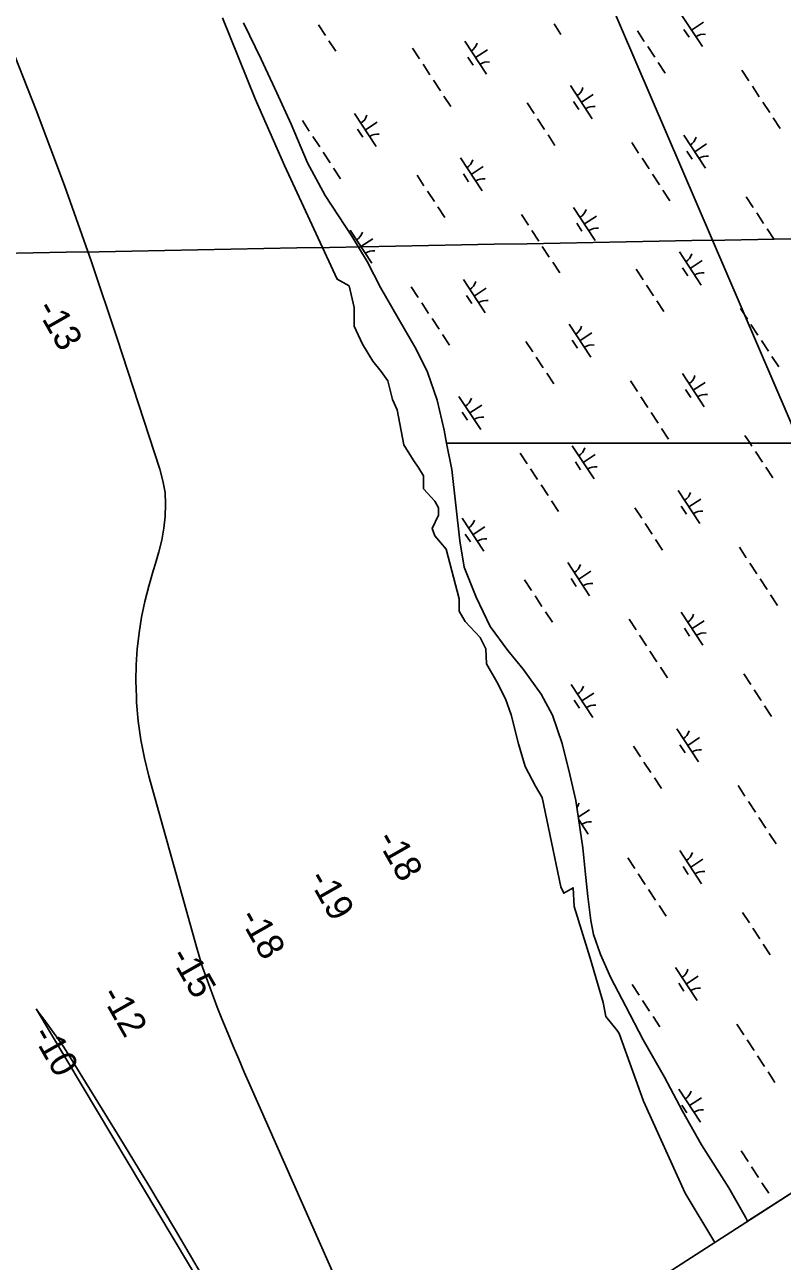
# Model space of a CAD drawing. Extents: x 3945642 to 3966284, y 206476 to 228921.
# Drawn here: x 3959667 to 3960623, y 211105 to 212666 of the extents above; entities that cross this region are included whole.
import ezdxf

# ---------------------------------------------------------------- set-up
doc = ezdxf.new("R2010")
doc.units = 0
for name, color, linetype in [('V-GRID-FRAM', 7, 'Continuous'), ('V-GRID-MAJR', 7, 'Continuous'), ('V-RIVR-EDGE', 7, 'Continuous'), ('V-RIVR-RANG', 7, 'Continuous'), ('V-TOPO-DPTH', 7, 'Continuous'), ('V-TOPO-MINR', 7, 'Continuous'), ('V-UTIL-LINE', 7, 'Continuous'), ('V-WETL-SWMP', 7, 'Continuous')]:
    doc.layers.add(name, color=color, linetype=linetype)

msp = doc.modelspace()

# ---------------------------------------------------------------- linework, layer by layer
at = {"layer": 'V-GRID-FRAM'}
msp.add_lwpolyline([(3956475, 226502.1), (3964764.2, 213849), (3957669.1, 209282.6), (3949512, 222000.5), (3956475, 226502.1)], dxfattribs=at)
at = {"layer": 'V-GRID-MAJR'}
msp.add_spline([(3955200.4, 212295.6), (3957056.9, 212329.8), (3962380.9, 212428.6), (3963931.2, 212457.5)], degree=3, dxfattribs=at)
at = {"layer": 'V-RIVR-EDGE'}
msp.add_lwpolyline([(3959916.3, 212675.1), (3959957.8, 212573), (3959994.6, 212488.7), (3960061.1, 212345), (3960076.5, 212336.7), (3960082.5, 212309.4), (3960082.5, 212285.7), (3960093.2, 212263.1), (3960106.2, 212241.7), (3960116.9, 212228.7), (3960125.2, 212216.8), (3960131.2, 212193.1), (3960137.1, 212180), (3960145.4, 212136.1), (3960157.3, 212117.1), (3960164.4, 212106.4), (3960170.3, 212096.9), (3960170.3, 212091), (3960170.3, 212080.3), (3960184.6, 212064.8), (3960189.3, 212056.5), (3960189.3, 212047), (3960181, 212030.4), (3960184.6, 212020.9), (3960198.8, 212004.3), (3960215.4, 211941.4), (3960215.4, 211925.9), (3960222.6, 211912.9), (3960241.6, 211892.7), (3960248.7, 211878.5), (3960249.9, 211859.5), (3960262.9, 211836.9), (3960273.6, 211815.5), (3960280.7, 211795.3), (3960290.2, 211758.5), (3960298.5, 211730), (3960311.6, 211705.1), (3960319.9, 211690.9), (3960343.7, 211578.1), (3960347.2, 211569.8), (3960359.1, 211576.9), (3960360.3, 211553.2), (3960380.5, 211487.9), (3960397.1, 211432.1), (3960400.6, 211414.3), (3960414.9, 211396.4), (3960417.3, 211392.9), (3960448.1, 211307.4), (3960500.4, 211191.1), (3960538.1, 211129.1)], dxfattribs=at)
at = {"layer": 'V-TOPO-DPTH'}
msp.add_line((3960046.8, 210812.9), (3959680.9, 211423.9), dxfattribs=at)
msp.add_lwpolyline([(3959680.9, 211423.9), (3959685.1, 211418.5), (3959690.9, 211410.8), (3959709.1, 211385.4), (3959712.1, 211381), (3959715.1, 211376.6), (3959718.1, 211372.1), (3959720.9, 211367.5), (3959786.7, 211260.9), (3959822.1, 211202.8), (3959857, 211144.4), (3959891.4, 211085.7), (3959925.3, 211026.8), (3960046.8, 210812.9)], dxfattribs=at)
at = {"layer": 'V-TOPO-MINR'}
for points in [[(3959643.8, 212653.8), (3959681, 212558.7), (3959716.8, 212463.2), (3959750.8, 212367), (3959783.5, 212270.3), (3959837.4, 212105.3), (3959841.2, 212090.6), (3959843.8, 212075.9), (3959844.5, 212060.9), (3959844, 212045.7), (3959842.1, 212030.6), (3959839.6, 212015.6), (3959836, 212000.8), (3959831.9, 211986.1), (3959828.9, 211976.9), (3959823.2, 211957.6), (3959818.3, 211938.2), (3959814.3, 211918.5), (3959811.1, 211898.7), (3959811, 211898.4), (3959808.8, 211878.3), (3959807.4, 211858.1), (3959807.1, 211837.9), (3959807.6, 211817.7), (3959808, 211810.8), (3959810, 211787.1), (3959813.1, 211763.7), (3959817.7, 211740.5), (3959823.3, 211717.5), (3959883.6, 211502.2), (3959887.4, 211489.3), (3959891.3, 211476.5), (3959895.7, 211463.8), (3959900.2, 211451.2), (3959904.9, 211438.6), (3959909.8, 211426.1), (3959914.8, 211413.6), (3959919.8, 211401.2), (3959923.1, 211393.1), (3959930, 211376.7), (3959936.9, 211360.4), (3959943.9, 211344), (3959951.1, 211327.8), (3960083.7, 211027.7)], [(3959680.9, 211423.9), (3959685.1, 211418.5), (3959690.9, 211410.8), (3959709.1, 211385.4), (3959712.1, 211381), (3959715.1, 211376.6), (3959718.1, 211372.1), (3959720.9, 211367.5), (3959786.7, 211260.9), (3959822.1, 211202.8), (3959857, 211144.4), (3959891.4, 211085.7), (3959925.3, 211026.8), (3960046.8, 210812.9)]]:
    msp.add_lwpolyline(points, dxfattribs=at)
at = {"layer": 'V-UTIL-LINE'}
msp.add_lwpolyline([(3960959.9, 211406.8), (3958349.2, 217477.4), (3962483, 212396.3)], dxfattribs=at)
at = {"layer": 'V-WETL-SWMP'}
for p, q in [((3960494.9, 212680.6), (3960522.3, 212638.8)), ((3959943, 212668.7), (3959965, 212622.9)), ((3960037.6, 212666.3), (3960046.4, 212652.9)), ((3960335, 212667.5), (3960343.8, 212654.1)), ((3960440.2, 212658.8), (3960449, 212645.4)), ((3960498.9, 212660.5), (3960505.5, 212650.5)), ((3960508.6, 212659.7), (3960523.7, 212669.6)), ((3960050.7, 212646.2), (3960059.5, 212632.9)), ((3960222.2, 212645.7), (3960249.6, 212603.9)), ((3960156.4, 212636.6), (3960165.2, 212623.2)), ((3960235.9, 212624.8), (3960251, 212634.6)), ((3960453.4, 212638.7), (3960462.2, 212625.3)), ((3959965, 212622.9), (3959984.9, 212580.4)), ((3960169.6, 212616.5), (3960178.3, 212603.1)), ((3960226.2, 212625.6), (3960232.7, 212615.5)), ((3960466.5, 212618.6), (3960475.3, 212605.2)), ((3960182.7, 212596.4), (3960191.5, 212583)), ((3960572.2, 212608.9), (3960581, 212595.6)), ((3959984.9, 212580.4), (3960003, 212541)), ((3960355.8, 212589.5), (3960383.2, 212547.6)), ((3960585.4, 212588.9), (3960594.1, 212575.5)), ((3960195.9, 212576.3), (3960204.6, 212563)), ((3960301.1, 212567.6), (3960309.9, 212554.2)), ((3960359.7, 212569.3), (3960366.3, 212559.3)), ((3960369.5, 212568.6), (3960384.5, 212578.4)), ((3960598.5, 212568.8), (3960607.3, 212555.4)), ((3960083.1, 212554.5), (3960110.5, 212512.7)), ((3960611.7, 212548.7), (3960620.4, 212535.3)), ((3960003, 212541), (3960023.8, 212491.9)), ((3960017.3, 212545.4), (3960026, 212532)), ((3960087, 212534.4), (3960093.6, 212524.4)), ((3960096.8, 212533.6), (3960111.8, 212543.5)), ((3960314.2, 212547.6), (3960323, 212534.2)), ((3960030.4, 212525.3), (3960039.2, 212512)), ((3960327.4, 212527.5), (3960336.2, 212514.1)), ((3960433.1, 212517.8), (3960441.8, 212504.4)), ((3960498.9, 212526.9), (3960526.3, 212485.1)), ((3960043.6, 212505.3), (3960052.3, 212491.9)), ((3960502.8, 212506.8), (3960509.4, 212496.8)), ((3960512.6, 212506), (3960527.6, 212515.9)), ((3960023.8, 212491.9), (3960046.1, 212450.6)), ((3960216.7, 212498.3), (3960244.1, 212456.5)), ((3960230.4, 212477.4), (3960245.4, 212487.3)), ((3960446.2, 212497.7), (3960455, 212484.3)), ((3960056.7, 212485.2), (3960065.5, 212471.8)), ((3960162, 212476.5), (3960170.7, 212463.1)), ((3960220.6, 212478.2), (3960227.2, 212468.2)), ((3960459.4, 212477.6), (3960468.1, 212464.3)), ((3960175.1, 212456.4), (3960183.9, 212443)), ((3960472.5, 212457.6), (3960481.3, 212444.2)), ((3960046.1, 212450.6), (3960079.5, 212399.4)), ((3960577.8, 212448.9), (3960586.5, 212435.5)), ((3960188.3, 212436.3), (3960197, 212422.9)), ((3960293.9, 212426.6), (3960302.7, 212413.3)), ((3960359.7, 212435.8), (3960387.1, 212393.9)), ((3960373.4, 212414.9), (3960388.5, 212424.7)), ((3960590.9, 212428.8), (3960599.7, 212415.4)), ((3960363.7, 212415.7), (3960370.3, 212405.6)), ((3960604.1, 212408.7), (3960612.8, 212395.3)), ((3960077.5, 212407.2), (3960104.9, 212365.3)), ((3960079.5, 212399.4), (3960099, 212367.4)), ((3960091.2, 212386.2), (3960106.3, 212396.1)), ((3960307.1, 212406.6), (3960315.9, 212393.2)), ((3960320.2, 212386.5), (3960329, 212373.1)), ((3960493.3, 212379.5), (3960520.7, 212337.7)), ((3960099, 212367.4), (3960115.8, 212334.8)), ((3960333.4, 212366.4), (3960342.2, 212353)), ((3960507, 212358.6), (3960522.1, 212368.5)), ((3960438.6, 212357.7), (3960447.4, 212344.3)), ((3960497.3, 212359.4), (3960503.8, 212349.4)), ((3960115.8, 212334.8), (3960138.3, 212295.8)), ((3960154.8, 212335.5), (3960163.6, 212322.1)), ((3960220.6, 212344.6), (3960248, 212302.8)), ((3960234.3, 212323.7), (3960249.3, 212333.6)), ((3960451.8, 212337.6), (3960460.5, 212324.2)), ((3960167.9, 212315.4), (3960176.7, 212302)), ((3960224.5, 212324.5), (3960231.1, 212314.5)), ((3960464.9, 212317.6), (3960473.7, 212304.2)), ((3960570.6, 212307.9), (3960579.4, 212294.5)), ((3960138.3, 212295.8), (3960161, 212256.8)), ((3960181.1, 212295.3), (3960189.9, 212282)), ((3960354.2, 212288.4), (3960381.6, 212246.6)), ((3960583.7, 212287.8), (3960592.5, 212274.4)), ((3960194.2, 212275.3), (3960203, 212261.9)), ((3960358.1, 212268.3), (3960364.7, 212258.2)), ((3960367.9, 212267.5), (3960382.9, 212277.3)), ((3960596.9, 212267.7), (3960605.7, 212254.3)), ((3960161, 212256.8), (3960175.2, 212227.6)), ((3960299.5, 212266.6), (3960308.2, 212253.2)), ((3960312.6, 212246.5), (3960321.4, 212233.1)), ((3960610, 212247.7), (3960618.8, 212234.3)), ((3960175.2, 212227.6), (3960187.4, 212192.2)), ((3960325.8, 212226.4), (3960334.6, 212213)), ((3960497.2, 212225.9), (3960524.6, 212184)), ((3960431.5, 212216.7), (3960440.2, 212203.3)), ((3960501.2, 212205.7), (3960507.8, 212195.7)), ((3960510.9, 212204.9), (3960526, 212214.8)), ((3960187.4, 212192.2), (3960196.1, 212154.6)), ((3960215, 212197.2), (3960242.4, 212155.4)), ((3960444.6, 212196.7), (3960453.4, 212183.3)), ((3960219, 212177.1), (3960225.6, 212167.1)), ((3960228.7, 212176.3), (3960243.8, 212186.2)), ((3960457.8, 212176.6), (3960466.5, 212163.2)), ((3960196.1, 212154.6), (3960199.4, 212137.9)), ((3960470.9, 212156.5), (3960479.7, 212143.1)), ((3960576.1, 212147.8), (3960582.6, 212137.9)), ((3960199.4, 212137.9), (3961225.2, 212137.9)), ((3961225.2, 212137.9), (3960199.4, 212137.9)), ((3960199.4, 212137.9), (3960206, 212104.9)), ((3960358.1, 212134.7), (3960385.5, 212092.9)), ((3960579.5, 211155.7), (3962105.5, 212137.9)), ((3960582.6, 212137.9), (3960584.9, 212134.4)), ((3960589.3, 212127.7), (3960598.1, 212114.3)), ((3960292.3, 212125.6), (3960301.1, 212112.2)), ((3960362.1, 212114.6), (3960368.6, 212104.5)), ((3960371.8, 212113.8), (3960386.9, 212123.7)), ((3960206, 212104.9), (3960216.1, 212014.6)), ((3960305.5, 212105.5), (3960314.2, 212092.1)), ((3960602.4, 212107.6), (3960611.2, 212094.3)), ((3960318.6, 212085.4), (3960327.4, 212072)), ((3960331.8, 212065.3), (3960340.5, 212052)), ((3960491.7, 212078.5), (3960519.1, 212036.7)), ((3960505.4, 212057.6), (3960520.4, 212067.4)), ((3960437, 212056.6), (3960445.8, 212043.3)), ((3960495.7, 212058.4), (3960502.2, 212048.3)), ((3960219, 212043.5), (3960246.4, 212001.7)), ((3960450.2, 212036.6), (3960458.9, 212023.2)), ((3960222.9, 212023.4), (3960229.5, 212013.4)), ((3960232.7, 212022.6), (3960247.7, 212032.5)), ((3960216.1, 212014.6), (3960221.7, 211981.7)), ((3960463.3, 212016.5), (3960472.1, 212003.1)), ((3960569, 212006.8), (3960577.7, 211993.4)), ((3960352.6, 211987.3), (3960380, 211945.5)), ((3960582.1, 211986.7), (3960590.9, 211973.3)), ((3960221.7, 211981.7), (3960236.8, 211943.8)), ((3960366.3, 211966.4), (3960381.3, 211976.3)), ((3960297.9, 211965.5), (3960306.6, 211952.1)), ((3960356.5, 211967.2), (3960363.1, 211957.2)), ((3960595.3, 211966.7), (3960604, 211953.3)), ((3960236.8, 211943.8), (3960254.5, 211906.6)), ((3960311, 211945.4), (3960319.8, 211932)), ((3960608.4, 211946.6), (3960617.2, 211933.2)), ((3960324.2, 211925.3), (3960332.9, 211912)), ((3960495.6, 211924.8), (3960523, 211883)), ((3960429.8, 211915.7), (3960438.6, 211902.3)), ((3960509.3, 211903.9), (3960524.4, 211913.7)), ((3960254.5, 211906.6), (3960276.8, 211876.2)), ((3960443, 211895.6), (3960451.8, 211882.2)), ((3960499.6, 211904.7), (3960506.2, 211894.6)), ((3960276.8, 211876.2), (3960296.2, 211852.7)), ((3960456.1, 211875.5), (3960464.9, 211862.1)), ((3960296.2, 211852.7), (3960318.9, 211821.4)), ((3960469.3, 211855.4), (3960478.1, 211842)), ((3960574.5, 211846.7), (3960583.3, 211833.3)), ((3960356.5, 211833.6), (3960383.9, 211791.8)), ((3960318.9, 211821.4), (3960332.9, 211794.7)), ((3960370.2, 211812.7), (3960385.2, 211822.6)), ((3960587.7, 211826.6), (3960596.4, 211813.3)), ((3960360.4, 211813.5), (3960367, 211803.5)), ((3960600.8, 211806.6), (3960609.6, 211793.2)), ((3960332.9, 211794.7), (3960345.3, 211758.9)), ((3960490.1, 211777.4), (3960517.5, 211735.6)), ((3960345.3, 211758.9), (3960354.9, 211719.6)), ((3960435.4, 211755.6), (3960444.1, 211742.2)), ((3960494, 211757.3), (3960500.6, 211747.2)), ((3960503.8, 211756.5), (3960518.8, 211766.4)), ((3960448.5, 211735.5), (3960457.3, 211722.1)), ((3960354.9, 211719.6), (3960362.5, 211686.8)), ((3960461.7, 211715.4), (3960470.5, 211702)), ((3960567.4, 211705.7), (3960576.1, 211692.4)), ((3960362.5, 211686.8), (3960371.4, 211627.4)), ((3960365.6, 211666), (3960379.7, 211675.2)), ((3960580.5, 211685.7), (3960589.3, 211672.3)), ((3960366, 211663.3), (3960378.3, 211644.4)), ((3960593.7, 211665.6), (3960602.4, 211652.2)), ((3960606.8, 211645.5), (3960615.6, 211632.1)), ((3960371.4, 211627.4), (3960374.3, 211597.9)), ((3960428.2, 211614.6), (3960437, 211601.2)), ((3960494, 211623.7), (3960521.4, 211581.9)), ((3960507.7, 211602.8), (3960522.8, 211612.7)), ((3960374.3, 211597.9), (3960377.7, 211565.9)), ((3960498, 211603.6), (3960504.5, 211593.6)), ((3960441.4, 211594.5), (3960450.1, 211581.1)), ((3960377.7, 211565.9), (3960381.4, 211535.3)), ((3960454.5, 211574.4), (3960463.3, 211561.1)), ((3960467.7, 211554.4), (3960476.4, 211541)), ((3960381.4, 211535.3), (3960384.7, 211517.8)), ((3960572.9, 211545.6), (3960581.7, 211532.3)), ((3960586.1, 211525.6), (3960594.8, 211512.2)), ((3960384.7, 211517.8), (3960393.5, 211492.5)), ((3960599.2, 211505.5), (3960608, 211492.1)), ((3960393.5, 211492.5), (3960406.8, 211463.1)), ((3960488.5, 211476.3), (3960515.9, 211434.5)), ((3960406.8, 211463.1), (3960425.3, 211427.6)), ((3960492.4, 211456.2), (3960499, 211446.2)), ((3960502.2, 211455.4), (3960517.2, 211465.3)), ((3960433.8, 211454.5), (3960442.5, 211441.1)), ((3960425.3, 211427.6), (3960447.5, 211384.7)), ((3960446.9, 211434.4), (3960455.7, 211421)), ((3960460.1, 211414.3), (3960468.8, 211401)), ((3960565.7, 211404.7), (3960574.5, 211391.3)), ((3960447.5, 211384.7), (3960474.6, 211337.6)), ((3960578.9, 211384.6), (3960587.7, 211371.2)), ((3960592, 211364.5), (3960600.8, 211351.1)), ((3960474.6, 211337.6), (3960497.4, 211294.9)), ((3960605.2, 211344.4), (3960614, 211331.1)), ((3960492.4, 211322.6), (3960519.8, 211280.8)), ((3960496.3, 211302.5), (3960502.9, 211292.5)), ((3960506.1, 211301.7), (3960521.1, 211311.6)), ((3960497.4, 211294.9), (3960521.2, 211252.3)), ((3960521.2, 211252.3), (3960555.9, 211197.8)), ((3960571.3, 211244.6), (3960580.1, 211231.2)), ((3960584.4, 211224.5), (3960593.2, 211211.1)), ((3960555.9, 211197.8), (3960576.9, 211160.7)), ((3960597.6, 211204.4), (3960606.4, 211191)), ((3960576.9, 211160.7), (3960579.5, 211155.7))]:
    msp.add_line(p, q, dxfattribs=at)
for centre, start, end in [((3960221, 212648), 302.4575, 344.0011), ((3960524, 212636.7), 82.4574, 124.0011), ((3960251.2, 212601.8), 82.4574, 124.0011), ((3960354.6, 212591.8), 302.4575, 344.0011), ((3960081.8, 212556.9), 302.4575, 344.0011), ((3960384.8, 212545.6), 82.4574, 124.0011), ((3960112.1, 212510.7), 82.4574, 124.0011), ((3960497.6, 212529.2), 302.4575, 344.0011), ((3960215.4, 212500.6), 302.4575, 344.0011), ((3960527.9, 212483), 82.4574, 124.0011), ((3960245.7, 212454.4), 82.4574, 124.0011), ((3960358.5, 212438.1), 302.4575, 344.0011), ((3960388.8, 212391.9), 82.4574, 124.0011), ((3960076.3, 212409.5), 302.4575, 344.0011), ((3960106.5, 212363.3), 82.4574, 124.0011), ((3960492.1, 212381.9), 302.4575, 344.0011), ((3960522.3, 212335.7), 82.4574, 124.0011), ((3960219.3, 212346.9), 302.4575, 344.0011), ((3960249.6, 212300.7), 82.4574, 124.0011), ((3960352.9, 212290.7), 302.4575, 344.0011), ((3960383.2, 212244.5), 82.4574, 124.0011), ((3960496, 212228.2), 302.4575, 344.0011), ((3960213.8, 212199.6), 302.4575, 344.0011), ((3960526.3, 212182), 82.4574, 124.0011), ((3960244.1, 212153.4), 82.4574, 124.0011), ((3960356.9, 212137), 302.4575, 344.0011), ((3960387.1, 212090.8), 82.4574, 124.0011), ((3960490.5, 212080.8), 302.4575, 344.0011), ((3960520.7, 212034.6), 82.4574, 124.0011), ((3960217.7, 212045.9), 302.4575, 344.0011), ((3960248, 211999.7), 82.4574, 124.0011), ((3960351.3, 211989.6), 302.4575, 344.0011), ((3960381.6, 211943.4), 82.4574, 124.0011), ((3960494.4, 211927.1), 302.4575, 344.0011), ((3960524.7, 211880.9), 82.4574, 124.0011), ((3960355.3, 211836), 302.4575, 344.0011), ((3960385.5, 211789.7), 82.4574, 124.0011), ((3960488.8, 211779.7), 302.4575, 344.0011), ((3960519.1, 211733.5), 82.4574, 124.0011), ((3960349.7, 211688.6), 323.1446, 344.0011), ((3960380, 211642.4), 82.4574, 124.0011), ((3960492.8, 211626), 302.4575, 344.0011), ((3960523, 211579.8), 82.4574, 124.0011), ((3960487.2, 211478.7), 302.4575, 344.0011), ((3960517.5, 211432.4), 82.4574, 124.0011), ((3960491.2, 211325), 302.4575, 344.0011), ((3960521.4, 211278.8), 82.4574, 124.0011)]:
    msp.add_arc(centre, 17.6, start, end, dxfattribs=at)

# ---------------------------------------------------------------- texts
at = {"layer": 'V-RIVR-RANG'}
for s, rotation, p in [('-13', 299.6087, (3959680.3, 212308.3)), ('-18', 299.5865, (3960109.9, 211638.2)), ('-19', 299.5865, (3960023.5, 211588.7)), ('-18', 299.5865, (3959936.4, 211539.7)), ('-15', 299.5865, (3959849, 211490.7)), ('-12', 299.5865, (3959761.9, 211441.8)), ('-10', 299.5865, (3959675.2, 211391.6))]:
    msp.add_text(s, height=33.5, rotation=rotation, dxfattribs=at).set_placement(p)

doc.saveas('drawing.dxf')
